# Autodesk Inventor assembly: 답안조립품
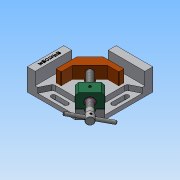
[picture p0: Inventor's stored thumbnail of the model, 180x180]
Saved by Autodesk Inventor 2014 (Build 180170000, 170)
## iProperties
Created: 2019-04
Part Number: 답안조립품
Document SubType Name: Assembly
Designer: NET
Author: NET
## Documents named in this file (11)
- C:\Users\NET\Desktop\답안조립품.iam
- C:\Users\NET\Desktop\본체.ipt
- C:\Users\NET\Desktop\490407v1029\리드스크류.ipt
- C:\Users\NET\Desktop\490407v1029\멈춤나사 M4x5.ipt
- C:\Users\NET\Desktop\490407v1029\멈춤나사 M4x10.ipt
- C:\Users\NET\Desktop\490407v1029\볼트 M4x16.ipt
- C:\Users\NET\Desktop\490407v1029\부시.ipt
- C:\Users\NET\Desktop\490407v1029\서포트.ipt
- C:\Users\NET\Desktop\490407v1029\평행 핀 2.5x24.ipt
- C:\Users\NET\Desktop\490407v1029\핸들.ipt
- C:\Users\NET\Desktop\490407v1029\조.ipt
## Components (1 placed, 1 different names)
1. 핸들:1
